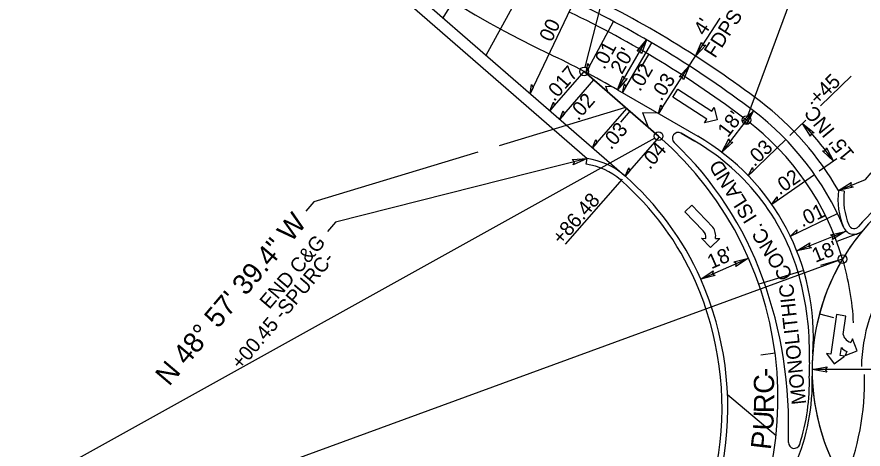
# Model space of a CAD drawing. Extents: x 1761082 to 1764358, y 421907 to 425434.
# Drawn here: x 1761873.7 to 1762165.7, y 422958.8 to 423108 of the extents above; entities that cross this region are included whole.
import ezdxf

# ---------------------------------------------------------------- set-up
doc = ezdxf.new("R2010")
doc.units = 0
for name, color, linetype in [('MARK HOOKS CENTER LEFT TURN ARROW CELL', 7, 'Continuous'), ('MARK HOOKS CENTER STRAIGHT LEFT TURN ARROW CELL', 7, 'Continuous'), ('MARK HOOKS STRAIGHT RIGHT TURN ARROW CELL', 7, 'Continuous'), ('MARK LEFT TURN ARROW CELL', 7, 'Continuous'), ('MARK STRAIGHT RIGHT ARROW CELL', 7, 'Continuous'), ('MARK UTURN ARROW CELL', 7, 'Continuous'), ('Prop Horizontal Alignment Tick Large', 7, 'Continuous'), ('Prop Mkg 3ft Min Skp 3ft Wide White', 7, 'Continuous'), ('Prop Mkg Min Skp 6ft Yellow', 7, 'Continuous'), ('Prop Mkg Skp Wht', 7, 'Continuous'), ('Prop Mkg Solid White Diagonals', 7, 'Continuous'), ('Prop Mkg Solid White Lane Line', 7, 'Continuous'), ('Prop Mkg Solid White Multiple Diagonals V8i', 7, 'Continuous'), ('Prop Mkg Solid White Stop Bar', 7, 'Continuous'), ('Prop Mkg Solid Yel Skip LT', 7, 'Continuous'), ('Prop Mkg Solid Yel Skip RT', 7, 'Continuous'), ('Prop Mkg Solid Yellow Diagonals', 7, 'Continuous'), ('Prop Mkg Solid Yellow Edge Line', 7, 'Continuous'), ('Prop Mkg Solid Yellow Lane Line', 7, 'Continuous'), ('Prop Mkr Yel 80ft Spc', 7, 'Continuous'), ('Scratch_Level_0', 7, 'Continuous'), ('Scratch_Level_5', 7, 'Continuous')]:
    doc.layers.add(name, color=color, linetype=linetype)

msp = doc.modelspace()

# ---------------------------------------------------------------- linework, layer by layer
at = {"layer": 'MARK HOOKS CENTER STRAIGHT LEFT TURN ARROW CELL'}
for p, q in [((1762091.68, 423095.08), (1762089.14, 423090.77)), ((1762085.23, 423075.43), (1762081.95, 423071.65)), ((1762150.65, 423005.53), (1762155.48, 423004.23)), ((1762135.31, 422991.92), (1762130.36, 422991.27))]:
    msp.add_line(p, q, dxfattribs=at)
at = {"layer": 'MARK LEFT TURN ARROW CELL'}
for p, q in [((1762070.16, 423057.15), (1762070.45, 423059.13)), ((1762159.15, 423047.79), (1762157.17, 423048.03))]:
    msp.add_line(p, q, dxfattribs=at)
for centre, radius, start, end in [((1762066.89, 423034.38), 23, 48.9609, 81.8208), ((1762223.1, 422986.12), 77, 115.1426, 139.959), ((1762016.33, 422976.3), 100, 23.7856, 48.9609), ((1762181.99, 423045.05), 23, 173.1545, 202.7054), ((1762162.62, 423036.94), 2, 202.7054, 319.959), ((1762009.01, 422973.08), 108, 319.7301, 23.7856)]:
    msp.add_arc(centre, radius, start, end, dxfattribs=at)
at = {"layer": 'MARK STRAIGHT RIGHT ARROW CELL'}
msp.add_line((1762095.12, 423066.81), (1762069.4, 423089.2), dxfattribs=at)
for centre, radius, start, end in [((1761913.61, 422793.76), 350, 52.7609, 64.5046), ((1762068.52, 422997.57), 94, 16.5895, 52.7609), ((1762016.33, 422976.3), 120, 319.7301, 48.9609)]:
    msp.add_arc(centre, radius, start, end, dxfattribs=at)
at = {"layer": 'MARK UTURN ARROW CELL'}
for points in [[(1762125.93, 423073.81), (1762189.69, 423246.02), (1762273.94, 423345.46)], [(1762069.77, 423090.65), (1762076.71, 423117.86)], [(1762083.71, 423076.75), (1762040.05, 423063.52)], [(1762093.81, 423066.09), (1761867.88, 422940.58), (1761783.27, 422840.7)], [(1762032.79, 423061.31), (1761976.18, 423044.16), (1761973.4, 423040.89)], [(1762157.2, 423023.89), (1761883.16, 422923.48), (1761800.37, 422825.75)]]:
    msp.add_lwpolyline(points, dxfattribs=at)
for centre in [(1762069.4, 423089.2), (1762125.41, 423072.41), (1762095.12, 423066.81), (1762158.61, 423024.41)]:
    msp.add_circle(centre, 1.5, dxfattribs=at)
at = {"layer": 'Prop Horizontal Alignment Tick Large'}
msp.add_line((1762158.61, 423024.41), (1762150.94, 423022.12), dxfattribs=at)
at = {"layer": 'Prop Mkg 3ft Min Skp 3ft Wide White'}
msp.add_line((1762095.12, 423066.81), (1762069.4, 423089.2), dxfattribs=at)
for centre, radius, start, end in [((1761913.61, 422793.76), 350, 52.7609, 64.5046), ((1762068.52, 422997.57), 94, 16.5895, 52.7609), ((1762016.33, 422976.3), 120, 319.7301, 48.9609), ((1762223.1, 422986.12), 75, 60.0363, 149.3002), ((1762223.1, 422986.12), 75, 149.3002, 219.4239)]:
    msp.add_arc(centre, radius, start, end, dxfattribs=at)
at = {"layer": 'Prop Mkg Skp Wht'}
msp.add_line((1761977.82, 423145.06), (1762083.3, 423053.24), dxfattribs=at)
for centre, radius, start, end in [((1761913.61, 422793.76), 354, 52.7609, 64.5046), ((1762068.52, 422997.57), 98, 22.7054, 52.7609), ((1762016.33, 422976.3), 102, 23.7856, 48.9609), ((1762162.62, 423036.94), 4, 202.7054, 319.959), ((1762009.01, 422973.08), 110, 319.7301, 23.7856)]:
    msp.add_arc(centre, radius, start, end, dxfattribs=at)
at = {"layer": 'Prop Mkg Solid White Diagonals'}
msp.add_line((1762107.61, 423065.07), (1762102.86, 423067.82), dxfattribs=at)
msp.add_lwpolyline([(1762144.11, 423016.81), (1762144.11, 423016.81)], dxfattribs=at)
for centre, radius, start, end in [((1762101.86, 423066.09), 2, 59.9275, 226.3932), ((1762016.33, 422976.3), 122, 19.9529, 46.3932), ((1762068.52, 422997.57), 78, 14.2778, 59.9275), ((1761990.01, 422966.75), 150, 357.8375, 19.9529), ((1762047.2, 422992.14), 100, 358.0377, 14.2776), ((1762223.1, 422986.12), 76, 178.0377, 181.6276), ((1762076.16, 422981.94), 71, 342.3411, 1.6276), ((1762141.91, 422961.01), 2, 177.8375, 342.3411)]:
    msp.add_arc(centre, radius, start, end, dxfattribs=at)
at = {"layer": 'Prop Mkg Solid White Lane Line'}
msp.add_line((1762102.86, 423067.82), (1762107.61, 423065.07), dxfattribs=at)
for centre, radius, start, end in [((1762101.86, 423066.09), 2, 59.9275, 226.3932), ((1762016.33, 422976.3), 122, 19.9529, 46.3932), ((1762068.52, 422997.57), 78, 14.2775, 59.9275), ((1761990.01, 422966.75), 150, 357.8375, 19.9529), ((1762047.2, 422992.14), 100, 358.0377, 14.2778), ((1762223.1, 422986.12), 76, 178.0377, 181.6276), ((1762076.16, 422981.94), 71, 342.3411, 1.6276), ((1762223.1, 422986.12), 76, 180.9467, 181.6276), ((1762141.91, 422961.01), 2, 177.8375, 342.3411)]:
    msp.add_arc(centre, radius, start, end, dxfattribs=at)
at = {"layer": 'Prop Mkg Solid White Multiple Diagonals V8i'}
for centre, radius, start, end in [((1762068.52, 422997.57), 94, 2.9334, 16.5895), ((1762223.1, 422986.12), 58, 146.1481, 178.8788), ((1762223.1, 422986.12), 75, 181.6276, 211.4287), ((1762076.16, 422981.94), 90, 337.1611, 1.6276)]:
    msp.add_arc(centre, radius, start, end, dxfattribs=at)
at = {"layer": 'Prop Mkg Solid White Stop Bar'}
msp.add_line((1761975.19, 423142.05), (1762070.45, 423059.13), dxfattribs=at)
for centre, radius, start, end in [((1761913.61, 422793.76), 358, 52.7609, 64.5046), ((1762068.52, 422997.57), 102, 29.6483, 52.7609), ((1762066.89, 423034.38), 25, 48.9609, 81.8208), ((1762181.99, 423045.05), 25, 173.1545, 202.7054)]:
    msp.add_arc(centre, radius, start, end, dxfattribs=at)
at = {"layer": 'Prop Mkg Solid Yel Skip RT'}
for p, q in [((1762105.69, 423091.12), (1762116.33, 423107.58)), ((1762080.97, 423082.81), (1762090.99, 423100.11)), ((1762161.58, 423087.5), (1762151.04, 423077.31)), ((1762127.83, 423075.59), (1762116.93, 423061.26)), ((1762145.96, 423072.4), (1762140.43, 423067.06)), ((1762156.62, 423058.97), (1762150.5, 423054.71)), ((1762062.95, 423029.49), (1762082.67, 423052)), ((1762142.82, 423027.23), (1762159.54, 423033.9)), ((1762109.67, 423017.44), (1762126.14, 423024.7)), ((1762298.1, 422985.98), (1762148.1, 422986.26))]:
    msp.add_line(p, q, dxfattribs=at)
for points in [[(1762070.45, 423059.13), (1761983.58, 423037.14), (1761980.81, 423033.88)], [(1762157.17, 423048.03), (1762166.56, 423051.92), (1762168.44, 423054.13)]]:
    msp.add_lwpolyline(points, dxfattribs=at)
msp.add_arc((1762068.52, 422997.57), 106, 34.8753, 44.0183, dxfattribs=at)
at = {"layer": 'Prop Mkg Solid Yellow Diagonals'}
for p, q in [((1762099.99, 423080.3), (1762101.78, 423083.08)), ((1762101.78, 423083.08), (1762113.54, 423075.48)), ((1762111.75, 423072.71), (1762099.99, 423080.3)), ((1762113.54, 423075.48), (1762114.35, 423076.74)), ((1762114.35, 423076.74), (1762115.32, 423072.43)), ((1762110.94, 423071.45), (1762111.75, 423072.71)), ((1762115.32, 423072.43), (1762110.94, 423071.45)), ((1762104.16, 423040.74), (1762106.54, 423043.03)), ((1762106.54, 423043.03), (1762113.85, 423035.43)), ((1762110.5, 423034.15), (1762104.16, 423040.74)), ((1762113.07, 423028.37), (1762109.92, 423031.58)), ((1762109.92, 423031.58), (1762111.4, 423031.55)), ((1762116.21, 423031.45), (1762113.07, 423028.37)), ((1762114.73, 423031.48), (1762116.21, 423031.45)), ((1762156.48, 423005.2), (1762154.53, 422991.54)), ((1762159.75, 423004.73), (1762156.48, 423005.2)), ((1762158.84, 422998.35), (1762159.75, 423004.73)), ((1762162.01, 422996.88), (1762161.42, 422995.56)), ((1762163.64, 422992.76), (1762162.01, 422996.88)), ((1762154.53, 422991.54), (1762153.04, 422991.75)), ((1762153.04, 422991.75), (1762155.72, 422988.24)), ((1762157.8, 422991.07), (1762158.2, 422993.89)), ((1762159.52, 422991.13), (1762163.64, 422992.76)), ((1762160.12, 422992.51), (1762159.52, 422991.13)), ((1762155.72, 422988.24), (1762159.28, 422990.86)), ((1762159.28, 422990.86), (1762157.8, 422991.07))]:
    msp.add_line(p, q, dxfattribs=at)
for centre, radius, start, end in [((1762109.57, 423032.41), 5.25, 349.8846, 35.1963), ((1762108.16, 423031.88), 3.27, 354.2142, 43.8724), ((1762161.35, 422998.64), 2.52, 186.4702, 222.7822), ((1762162.92, 422999.73), 4.43, 219.2921, 250.1457), ((1762161.62, 422996.69), 4.43, 219.3859, 250.2645)]:
    msp.add_arc(centre, radius, start, end, dxfattribs=at)
at = {"layer": 'Prop Mkg Solid Yellow Edge Line'}
for centre, radius, start, end in [((1762206.3, 423407.55), 346, 213.9873, 244.5046), ((1761913.61, 422793.76), 334, 62.1949, 64.5046), ((1762223.1, 422986.12), 75, 141.1818, 175.7628)]:
    msp.add_arc(centre, radius, start, end, dxfattribs=at)
at = {"layer": 'Prop Mkg Solid Yellow Lane Line'}
for points in [[(1762087.68, 423096.14), (1762090.99, 423100.11), (1762089.21, 423095.22), (1762088.75, 423096.24)], [(1762111.37, 423098.29), (1762107.86, 423094.48), (1762109.89, 423099.28), (1762110.29, 423098.24)], [(1762102.19, 423087.31), (1762105.69, 423091.12), (1762103.67, 423086.31), (1762103.26, 423087.35)], [(1762084.29, 423086.78), (1762080.97, 423082.81), (1762082.76, 423087.7), (1762083.22, 423086.68)], [(1762124.04, 423072.06), (1762127.83, 423075.59), (1762125.44, 423070.96), (1762125.11, 423072.02)], [(1762147.49, 423066.84), (1762144.75, 423071.23), (1762148.84, 423068), (1762147.73, 423067.89)], [(1762120.72, 423064.79), (1762116.93, 423061.26), (1762119.32, 423065.89), (1762119.64, 423064.83)], [(1762153.1, 423062.78), (1762155.48, 423058.18), (1762151.66, 423061.72), (1762152.78, 423061.75)], [(1762065.28, 423058.73), (1762070.45, 423059.13), (1762065.69, 423056.99), (1762066.1, 423058.03)], [(1762162.22, 423049.17), (1762157.17, 423048.03), (1762161.56, 423050.83), (1762161.31, 423049.74)], [(1762154.47, 423032.82), (1762159.54, 423033.9), (1762155.11, 423031.16), (1762155.38, 423032.24)], [(1762147.89, 423028.3), (1762142.82, 423027.23), (1762147.25, 423029.97), (1762146.98, 423028.89)], [(1762121.12, 423023.45), (1762126.14, 423024.7), (1762121.81, 423021.8), (1762122.04, 423022.89)], [(1762114.69, 423018.69), (1762109.67, 423017.44), (1762114, 423020.34), (1762113.77, 423019.25)], [(1762153.2, 422985.37), (1762148.1, 422986.26), (1762153.23, 422987.15), (1762152.58, 422986.25)]]:
    msp.add_lwpolyline(points, close=True, dxfattribs=at)
at = {"layer": 'Prop Mkr Yel 80ft Spc'}
for start, end in [(60.0363, 149.3002), (149.3002, 219.4239)]:
    msp.add_arc((1762223.1, 422986.12), 75, start, end, dxfattribs=at)
at = {"layer": 'Scratch_Level_0'}
for p, q in [((1762069.4, 423089.2), (1762095.12, 423066.81)), ((1762076.84, 423084.05), (1762077.65, 423082.02)), ((1762076.84, 423084.05), (1762078.9, 423083.99)), ((1762080.97, 423082.81), (1762108.61, 423066.8)), ((1762089.51, 423075), (1762094.69, 423074.86)), ((1762089.51, 423075), (1762091.54, 423069.93)), ((1762164.01, 423033.19), (1762156.59, 423030.43)), ((1762145.19, 423020.41), (1762129.65, 423015.78)), ((1762118.92, 422977.67), (1762135.65, 422963.49))]:
    msp.add_line(p, q, dxfattribs=at)
for centre, radius, start, end in [((1761913.61, 422793.76), 334, 59.9275, 62.1949), ((1762016.33, 422976.3), 120, 319.7301, 48.9609), ((1762068.52, 422997.57), 80, 355.7628, 59.9275), ((1762223.1, 422986.12), 75, 175.7628, 181.6276), ((1762076.16, 422981.94), 72, 336.6875, 1.6276)]:
    msp.add_arc(centre, radius, start, end, dxfattribs=at)
at = {"layer": 'Scratch_Level_5'}
for p, q in [((1762020.77, 423107.67), (1762034.78, 423130.32)), ((1762035.62, 423094.75), (1762050.15, 423121.38)), ((1762050.82, 423081.51), (1762065.98, 423113.29)), ((1762070.16, 423088.8), (1762079.53, 423106.47)), ((1762082.66, 423081.83), (1762092.78, 423099.07)), ((1762095.06, 423074.65), (1762105.69, 423091.12)), ((1762057.58, 423075.62), (1762069.4, 423089.2)), ((1762060.98, 423072.67), (1762072.8, 423086.25)), ((1762072.3, 423062.82), (1762084.11, 423076.4)), ((1762083.56, 423053.01), (1762095.43, 423066.55)), ((1762126.05, 423053.16), (1762139, 423065.67)), ((1762134.15, 423043.31), (1762148.92, 423053.61)), ((1762140.59, 423032.3), (1762156.8, 423040.12))]:
    msp.add_line(p, q, dxfattribs=at)
for points in [[(1762070.16, 423088.8), (1762070.68, 423091.92), (1762071.24, 423090.85)], [(1762050.82, 423081.51), (1762051.21, 423084.65), (1762051.82, 423083.6)], [(1762082.66, 423081.83), (1762083.31, 423084.92), (1762083.83, 423083.82)], [(1762057.58, 423075.62), (1762058.8, 423078.54), (1762059.1, 423077.37)], [(1762095.06, 423074.65), (1762095.84, 423077.71), (1762096.31, 423076.59)], [(1762060.98, 423072.67), (1762062.2, 423075.59), (1762062.5, 423074.41)], [(1762072.3, 423062.82), (1762073.51, 423065.74), (1762073.81, 423064.56)], [(1762083.56, 423053.01), (1762084.79, 423055.93), (1762085.09, 423054.75)], [(1762126.05, 423053.16), (1762127.51, 423055.97), (1762127.71, 423054.77)], [(1762134.15, 423043.31), (1762136.04, 423045.85), (1762136.05, 423044.64)], [(1762140.59, 423032.3), (1762142.86, 423034.51), (1762142.67, 423033.31)]]:
    msp.add_lwpolyline(points, close=True, dxfattribs=at)

# ---------------------------------------------------------------- texts
at = {"layer": 'MARK HOOKS CENTER LEFT TURN ARROW CELL'}
msp.add_text('N 48%%d 57\' 39.4" W', height=7, rotation=49.7301, dxfattribs=at).set_placement((1761926.21, 422980.23))
at = {"layer": 'MARK HOOKS STRAIGHT RIGHT TURN ARROW CELL'}
for s, rotation, p in [('-', 90.1873, (1762134.97, 422983.75)), ('C', 90.1873, (1762134.99, 422977.91)), ('R', 89.5725, (1762134.97, 422971.18)), ('U', 86.5894, (1762134.59, 422965.02)), ('P', 83.3385, (1762133.81, 422958.34))]:
    msp.add_text(s, height=7, rotation=rotation, dxfattribs=at).set_placement(p)
at = {"layer": 'Prop Mkg Min Skp 6ft Yellow'}
for s, rotation, p in [('00', 64.5046, (1762058.17, 423099.06)), ('.01', 62.0488, (1762076.4, 423089.59)), ('.017', 48.9609, (1762059.09, 423078.54)), ('.02', 59.5933, (1762088.69, 423081.98)), ('.03', 57.1378, (1762096.08, 423078.67)), ('.02', 48.9609, (1762067.38, 423071.95)), ("15' INC.", 129.4468, (1762162.94, 423060.77)), ('.03', 48.9609, (1762078.68, 423061.89)), ('.04', 48.7677, (1762092.04, 423055.06)), ('.03', 44.0183, (1762128.2, 423056.05)), ('.02', 34.8753, (1762136.86, 423046.34)), ('.01', 25.7324, (1762144.68, 423035.31))]:
    msp.add_text(s, height=5, rotation=rotation, dxfattribs=at).set_placement(p)
at = {"layer": 'Prop Mkg Solid Yel Skip LT'}
for s, rotation, p in [('FDPS', 57.1378, (1762114.61, 423093.49)), ("4'", 57.1378, (1762111.02, 423101.22)), ("20'", 59.9275, (1762082.45, 423087.91)), ('+45', 44.0183, (1762150.09, 423077.34)), ("18'", 52.7609, (1762119.04, 423066.12)), ('CONC. ISLAND', 122.0303, (1762141.67, 423018.92)), ('+86.48', 48.7677, (1762061.59, 423029)), ('END C&G', 49.7301, (1761960.8, 423006.8)), ("18'", 21.7596, (1762149.23, 423023.08)), ("18'", 23.7856, (1762113.3, 423020.84)), ('+00.45 -SPURC-', 49.7301, (1761950.96, 422985.9)), ('MONOLITHIC', 96.2583, (1762146.11, 422974.4))]:
    msp.add_text(s, height=5, rotation=rotation, dxfattribs=at).set_placement(p)

doc.saveas('drawing.dxf')
